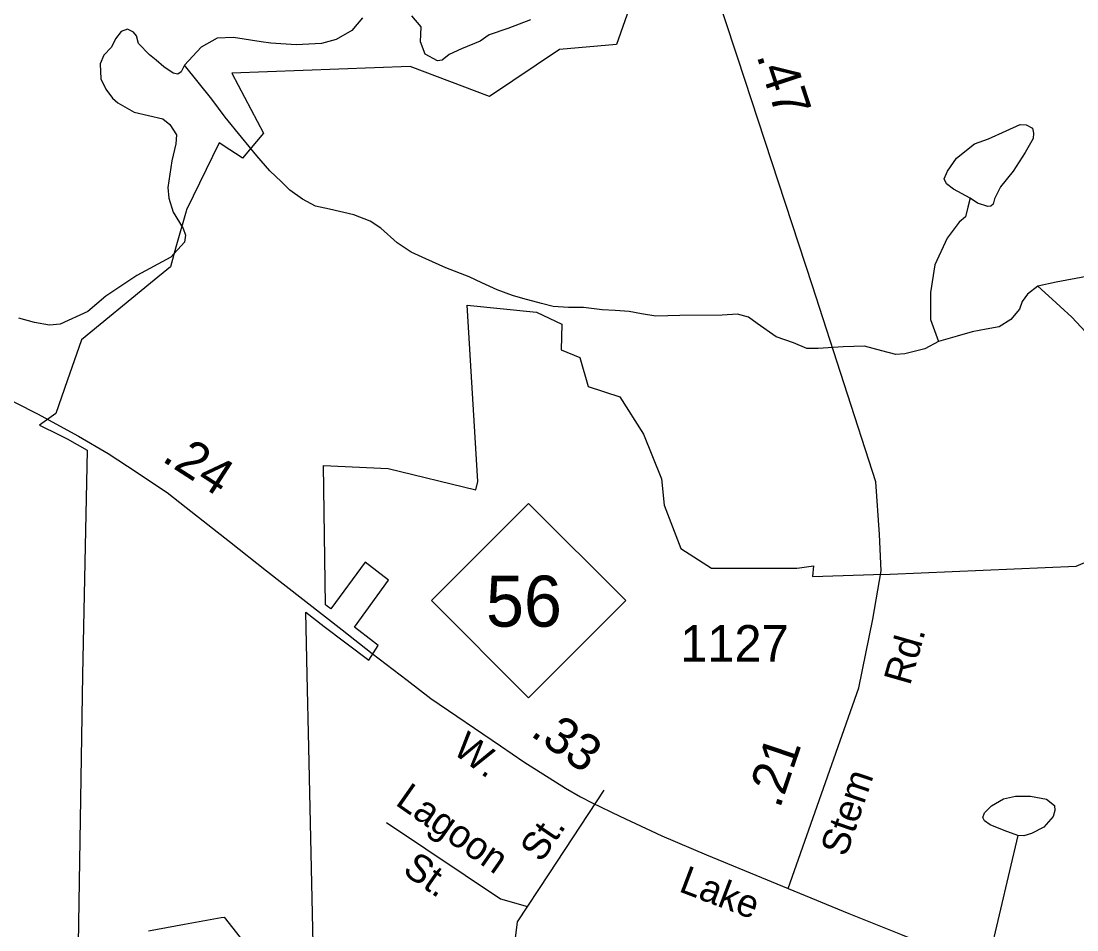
# Model space of a CAD drawing. Extents: x 2056842 to 2160602, y 826753 to 1016856.
# Drawn here: x 2087342 to 2090960, y 864126 to 867240 of the extents above; entities that cross this region are included whole.
import ezdxf

# ---------------------------------------------------------------- set-up
doc = ezdxf.new("R2010")
doc.units = 0
for name, color, linetype in [('Exist Boundary Political City Limit New', 7, 'Continuous'), ('Exist Hydrographic Creek Single Shore', 7, 'Continuous'), ('Exist Hydrographic Lake Shore', 7, 'Continuous'), ('Exist Hydrographic Misc Water Feature', 7, 'Continuous'), ('Exist Road Non-System Type 51', 7, 'Continuous'), ('Exist Road Non-System Type 51 Label', 7, 'Continuous'), ('Exist Road Primary NC Attributed', 7, 'Continuous'), ('Exist Road Primary NC Label', 7, 'Continuous'), ('Exist Road Primary NC Service Mileage Hundredths English Label', 7, 'Continuous'), ('Exist Road Primary NC Shield CELL', 7, 'Continuous'), ('Exist Road Primary NC Shield Number Label', 7, 'Continuous'), ('Exist Road Secondary Mileage Hundredths English Label', 7, 'Continuous'), ('Exist Road Secondary Type 51 Attributed', 7, 'Continuous'), ('Exist Road Secondary Type 51 Label', 7, 'Continuous'), ('Exist Road Secondary Type 51 Number Label', 7, 'Continuous'), ('Map Preparation Boundary City Limit Buffer Line', 7, 'Continuous')]:
    doc.layers.add(name, color=color, linetype=linetype)

msp = doc.modelspace()

# ---------------------------------------------------------------- linework, layer by layer
at = {"layer": 'Exist Boundary Political City Limit New'}
for points in [[(2089490.2, 867465.5), (2089382.6, 867159.8), (2089187, 867142.7), (2088947.5, 866982), (2088675.6, 867084.3), (2088064.4, 867062), (2088172.8, 866856.2), (2088101.1, 866770.6), (2088096.6, 866773.5), (2088057, 866799), (2088020.4, 866822.6), (2087908.5, 866593.2), (2087907.4, 866589.2), (2087872.2, 866464.8), (2087853.4, 866397.6), (2087785.4, 866341.8), (2087549.4, 866148.1), (2087500, 866007), (2087460.8, 865895), (2087405.5, 865855.8), (2087472, 865821.9), (2087500, 865808.4), (2087568, 865770), (2087552.5, 865000), (2087537.1, 864078.1)], [(2088484.9, 865162.9), (2088600.5, 865324.5), (2088521, 865385.5), (2088403.9, 865225.9), (2088390.8, 865235.5), (2088385.2, 865239.7), (2088377.9, 865716.6), (2088600.1, 865706.4), (2088900.6, 865633.4), (2088907.6, 865662.6), (2088870.4, 866266.4), (2089108.2, 866243), (2089195.5, 866201.9), (2089192.9, 866113.8), (2089256.9, 866087.8), (2089285.8, 865988.3), (2089393.8, 865952.3), (2089475, 865824.8), (2089537.1, 865671.4), (2089545.4, 865581.7), (2089603, 865432.6), (2089708.4, 865364.8), (2090000, 865365.9), (2090009, 865366), (2090057.8, 865373.2), (2090053.6, 865336.8), (2090229, 865342.8), (2090263, 865343.5), (2090320.6, 865345.3), (2090958.1, 865372.4), (2091361.1, 865543.2)], [(2088349.8, 863767.2), (2088328, 864750.7), (2088322.5, 865000), (2088318, 865214.3), (2088381, 865165.4), (2088533.5, 865049.9), (2088565.8, 865100.6), (2088550, 865112.8), (2088484.9, 865162.9)], [(2087778.8, 864122.4), (2087840.4, 864133.8), (2087902, 864145.1), (2087965.2, 864156.7), (2088027.5, 864168.1), (2088037.9, 864170), (2088092.1, 864100)]]:
    msp.add_lwpolyline(points, dxfattribs=at)
at = {"layer": 'Exist Hydrographic Creek Single Shore'}
for points in [[(2090485.7, 866142), (2090439.4, 866116.5), (2090370.7, 866100.3), (2090339.5, 866097.8), (2090292, 866110.3), (2090232, 866126.5), (2090159.6, 866124), (2090073.3, 866117.8), (2090034.6, 866117.8), (2089988.4, 866137.8), (2089929.7, 866157.8), (2089864.7, 866204.1), (2089834.7, 866225.3), (2089797.2, 866235.3), (2089744.7, 866232.8), (2089599.7, 866231.6), (2089517.6, 866229.4), (2089467.6, 866237), (2089425.6, 866245), (2089377.8, 866248.6), (2089333.5, 866250.8), (2089269.7, 866258.4), (2089217.9, 866258.2), (2089165.4, 866262.1), (2089125.4, 866271.8), (2089061.6, 866289.6), (2089025.5, 866299.5), (2088973, 866319.2), (2088921.3, 866343.3), (2088877.1, 866363.4), (2088797.3, 866395), (2088728.8, 866424.8), (2088678.8, 866448.6), (2088631, 866480.3), (2088574.8, 866530.2), (2088538.7, 866554.3), (2088482.5, 866575.8), (2088398.7, 866595.4), (2088350.5, 866605.6), (2088306.6, 866629.3), (2088262.5, 866661), (2088234, 866688.9), (2088194, 866727.1), (2088149.9, 866778.7), (2088097.7, 866842.7), (2088041.5, 866910.5), (2087995.5, 866972.2), (2087901.8, 867089.3)], [(2091466.5, 866572.6), (2091418.3, 866529.3), (2091390.4, 866505.1), (2091350.6, 866475), (2091314.7, 866450.9), (2091272.9, 866418.7), (2091232.7, 866392.6), (2091190.7, 866364.5), (2091136.7, 866358.3), (2091062.9, 866364.6), (2090993, 866364.6), (2090889.3, 866345.8), (2090826.8, 866332.1)], [(2090826.8, 866332.1), (2090790.5, 866304.6), (2090773.1, 866279.6), (2090763.1, 866253.3), (2090733.6, 866217.1), (2090693.4, 866192.8), (2090649.5, 866184.8), (2090601.5, 866174.7), (2090549.5, 866160.6), (2090485.7, 866142)]]:
    msp.add_lwpolyline(points, dxfattribs=at)
at = {"layer": 'Exist Hydrographic Lake Shore'}
for points in [[(2088511.6, 867250.7), (2088475.3, 867208.2), (2088421.6, 867176.5), (2088371.6, 867162.7), (2088284.2, 867159), (2088198, 867164), (2088164.2, 867169), (2088069.3, 867184), (2088014.3, 867181.5)], [(2089087.6, 867244.5), (2089010.1, 867214.5), (2088946.4, 867193.2), (2088915.2, 867170.7), (2088851.4, 867144.5), (2088809, 867125.7), (2088785.2, 867105.7), (2088769, 867104.4), (2088726.5, 867127), (2088710.2, 867169.5), (2088712.7, 867220.7), (2088681.5, 867258.2)], [(2087901.8, 867089.3), (2087890.5, 867065.6), (2087879.3, 867058.1), (2087863, 867061.8), (2087830.5, 867083.1), (2087804.3, 867105.6), (2087781.8, 867124.3), (2087744.3, 867163.1), (2087736.8, 867189.3), (2087726.8, 867201.8), (2087706.8, 867211.8), (2087684.3, 867204.3), (2087665.6, 867179.3), (2087651.9, 867150.6), (2087625.6, 867123.1), (2087613.1, 867093.1), (2087615.6, 867041.8), (2087631.9, 867006.8), (2087655.6, 866975.5), (2087673.1, 866959.9), (2087729.3, 866927.4), (2087828, 866904.9), (2087851.8, 866886.2), (2087874.3, 866849.9), (2087871.8, 866819.9), (2087858, 866761.1), (2087844.3, 866669.9), (2087848, 866633.6), (2087863, 866584.9), (2087896.8, 866528.9), (2087905.5, 866506.3), (2087901.8, 866482.6), (2087855.5, 866431.3), (2087738.1, 866368.8), (2087631.9, 866297.6), (2087570.6, 866245.1), (2087475.7, 866201.3), (2087439.4, 866197.6), (2087388.2, 866207.6), (2087334.5, 866222.6)], [(2088014.3, 867181.5), (2087959.3, 867150.2), (2087901.8, 867089.3)]]:
    msp.add_lwpolyline(points, dxfattribs=at)
at = {"layer": 'Exist Hydrographic Misc Water Feature'}
for points in [[(2090594.4, 866633.4), (2090536.9, 866664.4), (2090513.2, 866681.9), (2090505.7, 866699.4), (2090516.9, 866725.6), (2090548.1, 866770.6), (2090609.4, 866819.4), (2090656.9, 866836.9), (2090718.1, 866864.4), (2090765.6, 866885.7), (2090786.8, 866884.4), (2090808, 866873.2), (2090811.8, 866855.7), (2090810.5, 866838.1), (2090783, 866789.4), (2090741.8, 866725.6), (2090698.1, 866671.9), (2090678.1, 866630.6), (2090673.1, 866613.1), (2090665.6, 866605.6), (2090654.4, 866604.4), (2090619.4, 866615.6), (2090594.4, 866633.4)], [(2090594.4, 866633.4), (2090586.9, 866602.1), (2090578.1, 866569.6), (2090556.9, 866550.9), (2090515.7, 866495.8), (2090473.2, 866404.6), (2090458.2, 866309.6), (2090458.2, 866217.1), (2090485.7, 866142)], [(2091396.5, 865739.1), (2091342.8, 865772.9), (2091272.8, 865815.4), (2091212.9, 865855.4), (2091186.6, 865876.6), (2091172.2, 865896.6), (2091140.2, 865944.5), (2091102.1, 866000.2), (2091069.9, 866052.1), (2091037.7, 866114.3), (2091005.5, 866158), (2090943.2, 866225.9), (2090903.4, 866261.6), (2090874.9, 866287.4), (2090826.8, 866332.1)], [(2090757.3, 864449.4), (2090711.2, 864466.5), (2090662.4, 864486.3), (2090644, 864499.5), (2090637.4, 864511.3), (2090644, 864527.2), (2090667.7, 864550.9), (2090708.5, 864574.6), (2090749.4, 864583.8), (2090800.7, 864583.8), (2090856.1, 864573.3), (2090883.7, 864552.2), (2090885.1, 864535.1), (2090878.5, 864514), (2090846.9, 864478.4), (2090804.7, 864456), (2090778.3, 864448.1), (2090757.3, 864449.4)], [(2090757.3, 864449.4), (2090729.6, 864328.1), (2090658.1, 864026.5)]]:
    msp.add_lwpolyline(points, dxfattribs=at)
at = {"layer": 'Exist Road Non-System Type 51'}
for points in [[(2089339.3, 864604.4), (2089150.3, 864317.6), (2089042.3, 864153.4), (2089027.7, 864041.2), (2089019.4, 863983), (2088924.9, 863902.9), (2088835.6, 863855.1)], [(2088594.7, 864493.4), (2088864, 864313.3), (2088984.4, 864232.2), (2089077, 864206.2)]]:
    msp.add_lwpolyline(points, dxfattribs=at)
at = {"layer": 'Exist Road Primary NC Attributed'}
for points in [[(2087019.4, 866084), (2087174.4, 866006.8), (2087398.2, 865894.3), (2087538.1, 865817.7), (2087640.5, 865758.4), (2087706.6, 865715.3), (2087842, 865625.2), (2087908, 865573.2), (2088055.7, 865457.3), (2088182.7, 865356.1), (2088442.4, 865154.1), (2088545.3, 865072.4), (2088664.5, 864981.1), (2088746.2, 864918.5), (2088985.1, 864756.2), (2089065.2, 864701.9), (2089207.3, 864611.8), (2089259.3, 864582.2), (2089298.5, 864560.9), (2089393.7, 864515), (2089537.4, 864448.4), (2089691.3, 864383.5), (2089971.1, 864267.7)], [(2089971.1, 864267.7), (2090178.7, 864181.5), (2090355.3, 864111.6), (2090954.8, 863867.6), (2091051.6, 863825.7), (2091199.3, 863764.1), (2091326.3, 863710.4), (2091634.7, 863602.4)]]:
    msp.add_lwpolyline(points, dxfattribs=at)
at = {"layer": 'Exist Road Primary NC Shield CELL'}
msp.add_lwpolyline([(2088747.8, 865254.5), (2089080.8, 865587.5), (2089413.8, 865254.5), (2089080.8, 864921.5)], close=True, dxfattribs=at)
at = {"layer": 'Exist Road Secondary Type 51 Attributed'}
msp.add_lwpolyline([(2089971.1, 864267.7), (2090213.4, 864954.9), (2090261.1, 865190.4), (2090289.4, 865355.9), (2090284.2, 865480.4), (2090270.8, 865660.7), (2090054.1, 866332.3), (2089798.6, 867112.6), (2089559.5, 867836.3), (2089498.4, 868042), (2089471.6, 868186.6), (2089454.5, 868586.9), (2089448.8, 868784)], dxfattribs=at)
at = {"layer": 'Map Preparation Boundary City Limit Buffer Line'}
for points in [[(2089490.2, 867465.5), (2089382.6, 867159.8), (2089187, 867142.7), (2088947.5, 866982), (2088675.6, 867084.3), (2088064.4, 867062), (2088172.8, 866856.2), (2088101.1, 866770.6), (2088096.6, 866773.5), (2088057, 866799), (2088020.4, 866822.6), (2087908.5, 866593.2), (2087907.4, 866589.2), (2087872.2, 866464.8), (2087853.4, 866397.6), (2087785.4, 866341.8), (2087549.4, 866148.1), (2087500, 866007), (2087460.8, 865895), (2087405.5, 865855.8), (2087472, 865821.9), (2087500, 865808.4), (2087568, 865770), (2087552.5, 865000), (2087537.1, 864078.1)], [(2088484.9, 865162.9), (2088600.5, 865324.5), (2088521, 865385.5), (2088403.9, 865225.9), (2088390.8, 865235.5), (2088385.2, 865239.7), (2088377.9, 865716.6), (2088600.1, 865706.4), (2088900.6, 865633.4), (2088907.6, 865662.6), (2088870.4, 866266.4), (2089108.2, 866243), (2089195.5, 866201.9), (2089192.9, 866113.8), (2089256.9, 866087.8), (2089285.8, 865988.3), (2089393.8, 865952.3), (2089475, 865824.8), (2089537.1, 865671.4), (2089545.4, 865581.7), (2089603, 865432.6), (2089708.4, 865364.8), (2090000, 865365.9), (2090009, 865366), (2090057.8, 865373.2), (2090053.6, 865336.8), (2090229, 865342.8), (2090263, 865343.5), (2090320.6, 865345.3), (2090958.1, 865372.4), (2091361.1, 865543.2)], [(2088349.8, 863767.2), (2088328, 864750.7), (2088322.5, 865000), (2088318, 865214.3), (2088381, 865165.4), (2088533.5, 865049.9), (2088565.8, 865100.6), (2088550, 865112.8), (2088484.9, 865162.9)], [(2087778.8, 864122.4), (2087840.4, 864133.8), (2087902, 864145.1), (2087965.2, 864156.7), (2088027.5, 864168.1), (2088037.9, 864170), (2088092.1, 864100)]]:
    msp.add_lwpolyline(points, dxfattribs=at)

# ---------------------------------------------------------------- texts
at = {"layer": 'Exist Road Non-System Type 51 Label'}
for s, rotation, p in [('Lagoon', 325.0512, (2088620.7, 864556.7)), ('St.', 55.7957, (2089124.4, 864353.5)), ('St.', 325.0512, (2088645.2, 864321.7))]:
    msp.add_text(s, height=95, rotation=rotation, dxfattribs=at).set_placement(p)
at = {"layer": 'Exist Road Primary NC Label'}
for s, rotation, p in [('W.', 323.7315, (2088816.7, 864733.9)), ('Lake', 339.1737, (2089592.2, 864259))]:
    msp.add_text(s, height=95, rotation=rotation, dxfattribs=at).set_placement(p)
at = {"layer": 'Exist Road Primary NC Service Mileage Hundredths English Label'}
for s, rotation, p in [('.24', 327.1561, (2087820.5, 865734.9)), ('.33', 324.5944, (2089083.5, 864794))]:
    msp.add_text(s, height=125, rotation=rotation, dxfattribs=at).set_placement(p)
at = {"layer": 'Exist Road Primary NC Shield Number Label'}
msp.add_text('56', height=175, dxfattribs=at).set_placement((2088935, 865164.8))
at = {"layer": 'Exist Road Secondary Mileage Hundredths English Label'}
for s, rotation, p in [('.47', 288.1275, (2089861.4, 867121.6)), ('.21', 71.246, (2089941.9, 864538.8))]:
    msp.add_text(s, height=125, rotation=rotation, dxfattribs=at).set_placement(p)
at = {"layer": 'Exist Road Secondary Type 51 Label'}
for s, rotation, p in [('Rd.', 74.0906, (2090388.1, 864960.4)), ('Stem', 71.246, (2090169.1, 864373.3))]:
    msp.add_text(s, height=95, rotation=rotation, dxfattribs=at).set_placement(p)
at = {"layer": 'Exist Road Secondary Type 51 Number Label'}
msp.add_text('1127', height=125, dxfattribs=at).set_placement((2089600.6, 865045.2))

doc.saveas('drawing.dxf')
